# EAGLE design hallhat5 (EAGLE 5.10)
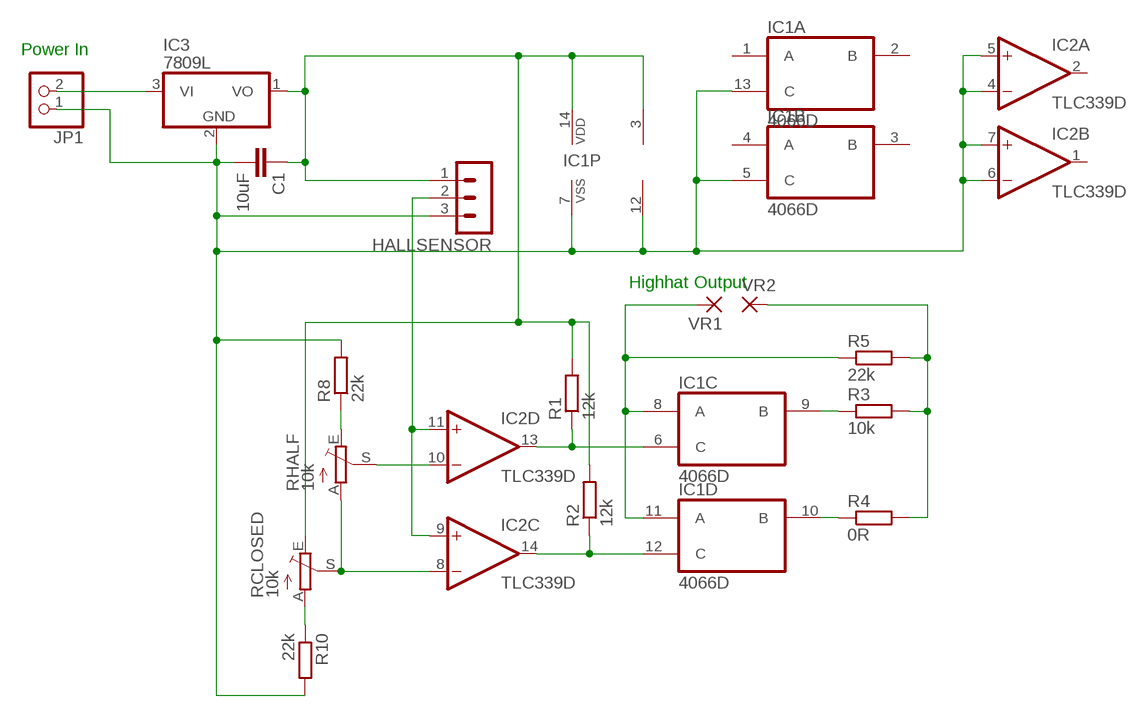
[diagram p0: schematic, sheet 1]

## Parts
C1  10uF  C-EUC1206  [C1206]
HALLSENSOR  MA03-1  [MA03-1]
IC1  4066D  [SO14]
IC2  TLC339D  [SO14]
IC3  7809L  7808L  [TO92]
JP1  PINHD-1X2  [1X02]
R1  12k  R-EU_R0805W  [R0805W]
R2  12k  R-EU_R0805W  [R0805W]
R3  10k  R-EU_0207/2V  [0207/2V]
R4  0R  R-EU_0207/2V  [0207/2V]
R5  22k  R-EU_0207/2V  [0207/2V]
R8  22k  R-EU_R0805  [R0805]
R10  22k  R-EU_R0805W  [R0805W]
RCLOSED  10k  TRIM_EU-B25U  [B25U]
RHALF  10k  TRIM_EU-B25U  [B25U]
VR1  1,6/0,9  [1,6/0,9]
VR2  1,6/0,9  [1,6/0,9]

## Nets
N$1: IC1.6(C:C) IC2.13(D:OUT) R1.1
N$2: IC1.12(D:C) IC2.14(C:OUT) R2.1
N$3: IC1.9(C:B) R3.1
N$4: IC2.10(D:-IN) RHALF.S
N$5: IC1.8(C:A) IC1.11(D:A) R5.1 VR1.1(P)
N$6: IC1.10(D:B) R4.1
N$8: R3.2 R4.2 R5.2 VR2.1(P)
N$9: C1.2 HALLSENSOR.3 IC1.5(B:C) IC1.7(P:VSS) IC1.13(A:C) IC2.4(A:-IN) IC2.5(A:+IN) IC2.6(B:-IN) IC2.7(B:+IN) IC2.12(P:V-) IC3.2(GND) JP1.1 R8.2 R10.2
N$10: IC2.8(C:-IN) RCLOSED.S RHALF.A
N$11: R8.1 RHALF.E
N$13: C1.1 HALLSENSOR.1 IC1.14(P:VDD) IC2.3(P:V+) IC3.1(VO) R1.2 R2.2 RCLOSED.E
N$14: R10.1 RCLOSED.A
N$21: IC3.3(VI) JP1.2
N$24: HALLSENSOR.2 IC2.9(C:+IN) IC2.11(D:+IN)
Unconnected: IC1.1(A:A) IC1.2(A:B) IC1.3(B:B) IC1.4(B:A) IC2.1(B:OUT) IC2.2(A:OUT)

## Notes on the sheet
- Power In
- Highhat Output

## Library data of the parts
C1 = rcl:C-EU: CAPACITOR, European symbol
HALLSENSOR = con-lstb:MA03-1: PIN HEADER
IC1 = 40xx:4066: Quad bilateral ANALOG SWITCH
IC2 = linear:TLC339: COMPARATOR
IC3 = linear:78*: Positive VOLTAGE REGULATOR Source: http://cache.national.com/ds/LM/LM78L05.pdf http://www.fairchildsemi.com/ds/LM/LM7805.pdf
JP1 = pinhead:PINHD-1X2: PIN HEADER
R1-R5 R8 R10 = rcl:R-EU_: RESISTOR, European symbol
RCLOSED RHALF = pot:TRIM_EU-: POTENTIOMETER
VR1 VR2 = wirepad:1,6/0,9: THROUGH-HOLE PAD

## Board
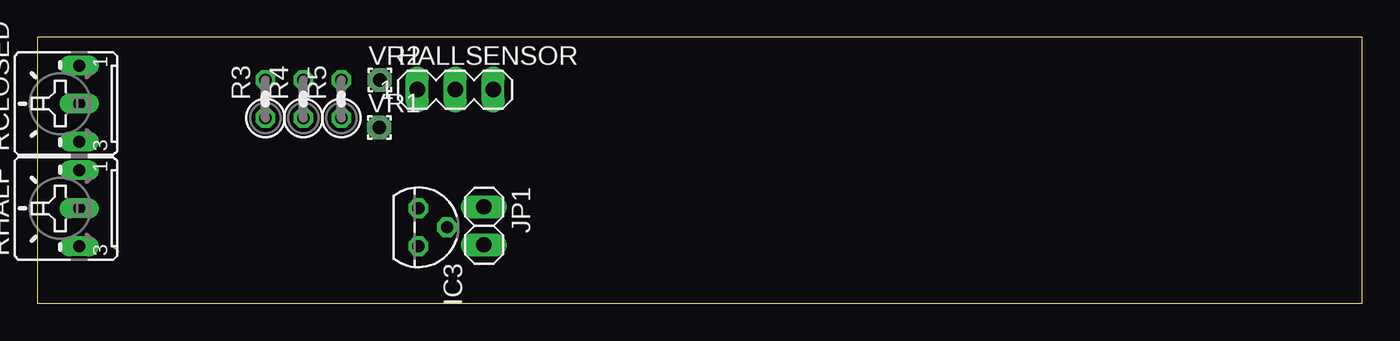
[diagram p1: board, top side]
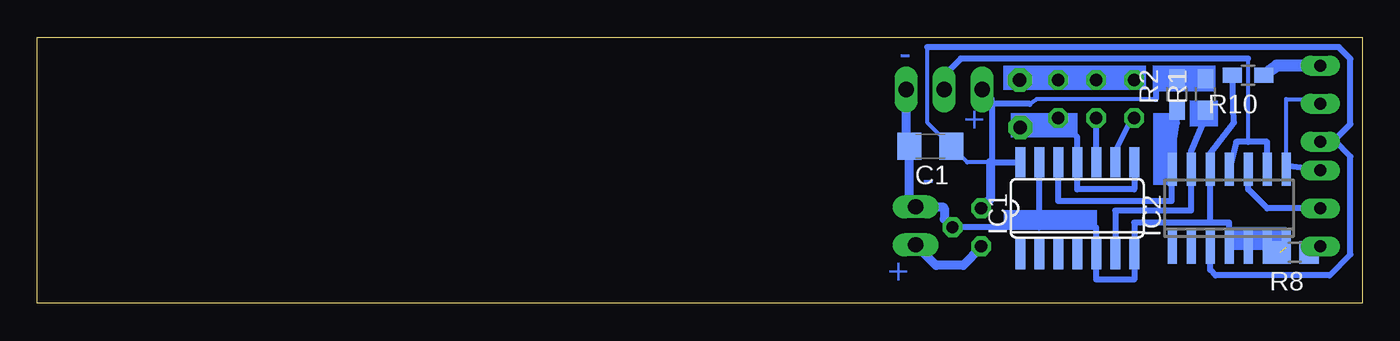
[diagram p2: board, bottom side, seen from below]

Size 88.57 x 17.77 mm. Coordinates in mm from the lower left corner, seen from the top.
Outline: 0,0 88.57,0 88.57,17.77 0,17.77 0,0
Copper layers (1*16): Top 0.035mm / dielectric 1.5mm / Bottom 0.035mm
Design rules "default": minimum track width 10mil, minimum drill 24mil, track to track 8mil, track to pad 8mil, pad to pad 8mil, via to via 8mil, smd to smd 8mil, copper to edge 40mil, drill to drill 8mil, minimum pad ring 10mil, minimum via ring 8mil, stop-mask expansion 4mil, vias tented up to drill 0mil, thermal gap 10mil

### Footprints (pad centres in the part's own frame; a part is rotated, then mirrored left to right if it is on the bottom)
C1206 = smd 1.6 x 1.8: 1 -1.4,0; 2 1.4,0
MA03-1 = drill 1.016 long: 1 -2.54,0; 2 0,0; 3 2.54,0
SO14 = smd 0.66 x 2.032: 1 -3.81,-3.073; 2 -2.54,-3.073; 3 -1.27,-3.073; 4 0,-3.073; 5 1.27,-3.073; 6 2.54,-3.073; 7 3.81,-3.073; 8 3.81,3.073; 9 2.54,3.073; 10 1.27,3.073; 11 0,3.073; 12 -1.27,3.073; 13 -2.54,3.073; 14 -3.81,3.073
SO14' = smd 0.6 x 2.2: 1 -3.81,-2.6; 2 -2.54,-2.6; 3 -1.27,-2.6; 4 0,-2.6; 5 1.27,-2.6; 6 2.54,-2.6; 7 3.81,-2.6; 8 3.81,2.6; 9 2.54,2.6; 10 1.27,2.6; 11 0,2.6; 12 -1.27,2.6; 13 -2.54,2.6; 14 -3.81,2.6
TO92 = drill 0.813 octagon: 1 -1.27,0; 2 0,1.905; 3 1.27,0
1X02 = drill 1.016 long: 1 -1.27,0; 2 1.27,0
R0805W = smd 1.27 x 1.016: 1 -1.052,0; 2 1.052,0
0207/2V = drill 0.813 octagon: 1 -1.27,0; 2 1.27,0
R0805 = smd 1.3 x 1.5: 1 -0.95,0; 2 0.95,0
B25U = drill 0.813 long: A 2.54,-0.889; E -2.54,-0.889; S 0,-0.889
1,6/0,9 = drill 0.914 pad 1.6 octagon: 1 0,0

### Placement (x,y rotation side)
C1  28.87,10.5 180 bottom
HALLSENSOR  27.94,14.29 0 top
IC1  19.05,6.35 0 bottom
IC2  TLC339D  [SO14']  8.89,6.35 0 bottom
IC3  25.48,5.08 270 top
JP1  29.85,5.17 270 top
R1  10.47,13.97 90 bottom
R2  12.38,13.97 90 bottom
R3  15.24,13.65 90 top
R4  17.78,13.65 90 top
R5  20.32,13.65 90 top
R8  4.51,3.4 180 bottom
R10  7.62,15.24 180 bottom
RCLOSED  1.91,13.34 90 top
RHALF  1.91,6.34 90 top
VR1  22.86,11.75 0 top
VR2  22.89,14.92 0 top

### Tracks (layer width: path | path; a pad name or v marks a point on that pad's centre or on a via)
N$1
  Bottom 0.406: IC1.6 16.51,6.19 11.43,6.19 IC2.13 11.43,10.16 10.47,12.38 R1.1
N$2
  Bottom 0.406: IC1.12 20.32,6.83 12.72,6.83 IC2.14 12.7,10.16 12.38,12.06 R2.1
N$3
  Bottom 0.406: R3.1 15.24,12.7 16.51,10.16 IC1.9
N$4
  Bottom 0.406: RHALF.S 6.34,6.34 7.62,7.62 IC2.10
N$5
  Bottom 0.406: IC1.8 15.24,7.62 19.05,7.62 IC1.11 19.05,11.11 R5.1 21.59,12.38 VR1.1
N$6
  Bottom 0.406: IC1.10 R4.1
N$8
  Bottom 0.406: R3.2 R4.2 R5.2 VR2.1
N$9  (1 unrouted)
  Bottom 0.254: C1.2 30.48,10.96
  Bottom 0.406: 10.16,5.4 15.24,5.4 IC1.7 15.24,1.59 17.78,1.59 IC1.5 17.78,5.08 21.59,5.08 | 10.16,5.4 IC2.12 10.16,10.01 8.57,12.07 R10.2 | 21.59,5.08 IC3.2 | 21.59,5.08 IC1.13 | 10.16,5.4 8.89,5.4 IC2.4 IC2.5 IC2.6 IC2.7
  Bottom 0.61: 30.48,10.96 HALLSENSOR.3 | C1.2 30.27,6.86 JP1.1 28.03,6.44 27.94,6.35 27.94,5.64 IC3.2
N$10
  Bottom 0.254: 3.81,13.65 5.08,13.65 IC2.8
  Bottom 0.406: 3.81,13.65 RCLOSED.S | RHALF.A 5.17,9.2 IC2.8
N$11
  Bottom 0.406: RHALF.E 3.51,4.12 R8.1
N$13
  Bottom 0.254: 13.8,13.65 21.76,13.65 22.23,13.34 | R1.2 R2.2 | 29.09,17.11 29.09,12.12 C1.1 26.4,9.42 24.87,9.42
  Bottom 0.406: R2.2 11.65,15.02 | IC1.14 24.87,9.42 24.77,9.53 24.77,13.34 | 22.23,13.34 24.77,13.34 | R2.2 11.48,14.97 | 24.77,13.34 24.77,13.65 HALLSENSOR.1 | 13.8,13.65 13.8,14.92 12.06,14.92 R2.2 | 10.16,14.92 R1.2 10.16,15.24 | IC2.3 10.16,2.23 9.8,1.87 2.18,1.87 0.78,3.27 0.78,9.8 1.87,10.89 2.71,10.89 RCLOSED.E 1.96,10.8 0.78,11.98 0.78,16.34 1.56,17.11 29.09,17.11
  Bottom 0.61: 24.87,9.42 24.87,6.96 IC3.1
N$14
  Bottom 0.813: RCLOSED.A 5.72,15.88 R10.1
N$21
  Bottom 0.61: IC3.3 25.48,3.73 26.67,2.54 28.49,2.54 JP1.2
N$24
  Bottom 0.254: 7.62,10.79 7.62,16.35
  Bottom 0.406: IC2.11 8.42,10.79 7.62,10.79 6.35,10.79 IC2.9 | 7.62,16.35 26.83,16.36 27.94,15.24 HALLSENSOR.2
(copper drawn outside any net)
  shapes: Bottom area x7

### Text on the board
Bottom: - | + | - | +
